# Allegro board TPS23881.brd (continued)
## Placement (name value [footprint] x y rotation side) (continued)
CB142  0.1U/6.3V/X5R-C1  [SM0201_C]  126.11 34.16 90 bottom
CB143  0.1U/6.3V/X5R-C1  [SM0201_C]  107.82 33.78 90 bottom
CB144  0.1U/6.3V/X5R-C1  [SM0201_C]  89.53 33.78 90 bottom
CB145  0.1U/6.3V/X5R-C1  [SM0201_C]  71.25 33.78 90 bottom
CB146  0.1U/6.3V/X5R-C1  [SM0201_C]  52.96 33.78 90 bottom
CB147  0.1U/6.3V/X5R-C1  [SM0201_C]  34.67 33.78 90 bottom
CB148  0.1U/6.3V/X5R-C1  [SM0201_C]  30.86 32.64 0 bottom
CB149  0.1U/6.3V/X5R-C1  [SM0201_C]  139.06 30.1 0 bottom
CB150  0.1U/6.3V/X5R-C1  [SM0201_C]  120.78 29.72 0 bottom
CB151  0.1U/6.3V/X5R-C1  [SM0201_C]  102.49 29.72 0 bottom
CB152  0.1U/6.3V/X5R-C1  [SM0201_C]  84.2 29.72 0 bottom
CB153  0.1U/6.3V/X5R-C1  [SM0201_C]  65.91 29.72 0 bottom
CB154  0.1U/6.3V/X5R-C1  [SM0201_C]  47.62 29.72 0 bottom
CE1  POS-16TQC100MYF  [SM2917_CD19]  44.45 187.96 90 top
CE2  POS-6TPE221MAP  [SM2917_CD19]  152.02 185.8 270 top
CE3  HEC-100U/80V-FVF  [SMEC103X103_165]  36.45 170.56 0 top
CE4  HEC-100U/80V-FVF  [SMEC103X103_165]  24.89 162.18 180 top
CE5  HEC-100U/80V-FVF  [SMEC103X103_165]  9.65 161.04 0 top
CE6  HEC-100U/80V-FVF  [SMEC103X103_165]  28.06 114.59 0 top
CE7  HEC-100U/80V-FVF  [SMEC103X103_165]  28.04 103.75 0 top
CE8  POS-100U/6.3V-TPE  [SM1512_CB20]  132.87 103 270 top
CE9  POS-100U/6.3V-TPE  [SM1512_CB20]  119.28 93.47 270 top
CE10  POS-6TPE220MAZB  [SM1512_CB20]  126.77 85.85 0 top
CE11  POS-6TPE220MAZB  [SM1512_CB20]  99.01 60.15 270 top
CE12  POS-6TPE220MAZB  [SM1512_CB20]  77.8 55.19 90 top
CE13  POS-6TPE220MAZB  [SM1512_CB20]  64.85 53.7 90 top
CM1  0.22U/16V/X7R-C2  [SM0402_C]  147.41 121.3 270 top
CM2  1U/10V/X5R-C2  [SM0402_C]  61.29 63.83 0 top
CM3  1U/10V/X5R-C2  [SM0402_C]  46.23 67.06 180 top
CM4  1U/10V/X5R-C2  [SM0402_C]  55.37 72.64 90 top
CM5  1U/10V/X5R-C2  [SM0402_C]  61.29 64.85 0 top
CM6  1U/10V/X5R-C2  [SM0402_C]  61.29 61.8 0 top
CM7  1U/10V/X5R-C2  [SM0402_C]  52.96 72.64 90 top
CM8  1U/10V/X5R-C2  [SM0402_C]  61.29 59.64 0 top
CM9  1U/10V/X5R-C2  [SM0402_C]  46.23 63.5 180 top
CM10  1U/10V/X5R-C2  [SM0402_C]  46.23 60.83 180 top
CM11  1U/10V/X5R-C2  [SM0402_C]  51.89 57.73 270 top
CM12  1U/10V/X5R-C2  [SM0402_C]  55.37 57.78 270 top
CM13  1U/10V/X5R-C2  [SM0402_C]  57.78 72.64 90 top
CM14  1U/10V/X5R-C2  [SM0402_C]  51.94 72.64 90 top
CM15  1U/10V/X5R-C2  [SM0402_C]  57.78 57.78 270 top
CM16  1U/10V/X5R-C2  [SM0402_C]  52.96 57.78 270 top
CM17  1U/10V/X5R-C2  [SM0402_C]  46.23 62.23 180 top
CM18  1U/10V/X5R-C2  [SM0402_C]  61.29 60.66 0 top
CM19  1U/10V/X5R-C2  [SM0402_C]  54.15 72.64 90 top
CM20  1U/10V/X5R-C2  [SM0402_C]  61.29 62.81 0 top
CM21  1U/10V/X5R-C2  [SM0402_C]  56.57 57.78 270 top
CM22  1U/10V/X5R-C2  [SM0402_C]  56.57 72.64 90 top
CM23  1U/10V/X5R-C2  [SM0402_C]  54.1 57.78 270 top
CM24  1U/10V/X5R-C2  [SM0402_C]  46.81 71.96 180 top
CM25  0.22U/16V/X7R-C2  [SM0402_C]  137.92 121.28 270 top
CM26  0.22U/16V/X7R-C2  [SM0402_C]  139.06 121.28 270 top
CM27  0.22U/16V/X7R-C2  [SM0402_C]  142.11 121.28 270 top
CM28  0.22U/16V/X7R-C2  [SM0402_C]  143.26 121.28 270 top
CM29  0.22U/16V/X7R-C2  [SM0402_C]  146.3 121.28 270 top
CM30  0.22U/16V/X7R-C2  [SM0402_C]  150.5 121.28 270 top
CM31  0.22U/16V/X7R-C2  [SM0402_C]  151.64 121.28 270 top
CM32  -  [SM0402_C]  53.85 112.48 90 top
CM33  -  [SM0402_C]  54.86 112.48 90 top
CM34  -  [SM0402_C]  56.32 112.48 90 top
CM35  -  [SM0402_C]  57.34 112.48 90 top
CM36  -  [SM0402_C]  58.74 112.48 90 top
CM37  -  [SM0402_C]  59.75 112.48 90 top
CM38  -  [SM0402_C]  61.21 112.48 90 top
CM39  -  [SM0402_C]  62.23 112.48 90 top
CM40  -  [SM0402_C]  55.12 109.05 90 top
CM41  -  [SM0402_C]  56.13 109.05 90 top
CM42  -  [SM0402_C]  59.94 108.93 90 top
CM43  -  [SM0402_C]  60.96 108.93 90 top
CM44  0.22U/16V/X7R-C2  [SM0402_C]  91.34 99.16 180 top
CM45  0.22U/16V/X7R-C2  [SM0402_C]  96.84 95 180 top
CM46  -  [SM0402_C]  66.29 84.58 270 top
CM47  -  [SM0402_C]  67.31 84.58 270 top
CM48  -  [SM0402_C]  55.68 83.44 270 top
CM49  -  [SM0402_C]  56.69 83.44 270 top
CM50  -  [SM0402_C]  53.04 77.34 90 top
CM51  -  [SM0402_C]  54.05 77.34 90 top
CM52  -  [SM0402_C]  55.45 77.34 90 top
CM53  -  [SM0402_C]  56.46 77.34 90 top
CM54  -  [SM0402_C]  54.23 75.18 90 top
CM55  -  [SM0402_C]  55.24 75.18 90 top
CM56  -  [SM0402_C]  56.64 75.18 90 top
CM57  -  [SM0402_C]  57.66 75.18 90 top
CM58  -  [SM0402_C]  43.94 63.37 180 top
CM59  -  [SM0402_C]  43.94 62.36 180 top
CM60  -  [SM0402_C]  55.5 55.37 270 top
CM61  -  [SM0402_C]  56.52 55.37 270 top
CM62  -  [SM0402_C]  54.23 52.32 270 top
CM63  -  [SM0402_C]  55.24 52.32 270 top
CM64  0.22U/16V/X7R-C2  [SM0402_C]  140.08 179.07 0 bottom
CM65  0.22U/16V/X7R-C2  [SM0402_C]  130.94 141.48 270 bottom
CM66  0.22U/16V/X7R-C2  [SM0402_C]  138.94 121.03 90 bottom
CM67  0.22U/16V/X7R-C2  [SM0402_C]  137.92 121.03 90 bottom
CM68  -  [SM0402_C]  58.55 108.97 90 bottom
CM69  -  [SM0402_C]  57.53 108.97 90 bottom
CM70  -  [SM0402_C]  63.37 108.93 90 bottom
CM71  -  [SM0402_C]  62.36 108.93 90 bottom
CM72  0.22U/16V/X7R-C2  [SM0402_C]  140.74 100.08 180 bottom
CM73  -  [SM0402_C]  62.1 83.44 270 bottom
CM74  -  [SM0402_C]  61.09 83.44 270 bottom
CM75  -  [SM0402_C]  58.88 83.44 270 bottom
CM76  -  [SM0402_C]  57.86 83.44 270 bottom
CM77  -  [SM0402_C]  68.45 83.31 270 bottom
CM78  -  [SM0402_C]  67.44 83.31 270 bottom
CM79  -  [SM0402_C]  124.59 47.19 180 bottom
CM80  -  [SM0402_C]  124.59 46.18 180 bottom
CM81  -  [SM0402_C]  23.06 39.37 90 bottom
CM82  -  [SM0402_C]  22.05 39.37 90 bottom
CM83  -  [SM0402_C]  131.27 37.08 90 bottom
CM84  -  [SM0402_C]  130.25 37.08 90 bottom
CM85  -  [SM0402_C]  112.98 36.7 90 bottom
CM86  -  [SM0402_C]  111.96 36.7 90 bottom
CM87  -  [SM0402_C]  94.69 36.7 90 bottom
CM88  -  [SM0402_C]  93.68 36.7 90 bottom
CM89  -  [SM0402_C]  76.4 36.7 90 bottom
CM90  -  [SM0402_C]  75.39 36.7 90 bottom
CM91  -  [SM0402_C]  58.12 36.7 90 bottom
CM92  -  [SM0402_C]  57.1 36.7 90 bottom
CM93  -  [SM0402_C]  39.83 36.7 90 bottom
CM94  -  [SM0402_C]  38.81 36.7 90 bottom
CN1  USB3.2-9F-A-RA  [USB3A_WU3R-09]  108.03 66.61 90 bottom
CN2  USB3.1-GEN2-A  [USB31AV_UAA131C-40021]  82.35 45.68 0 bottom
CV1  1000P/2KV-C6  [SM1206_C]  26.37 13.67 270 top
CV8  1000P/2KV-C6  [SM1206_C]  151.76 42.29 90 top
D1  BAT54C  [SOT23-AAC]  74.57 142.88 90 bottom
D2  BAT54H  [SOD323]  87.53 106.05 90 top
D5  YEU25CA0505AC  [DFN10_2D5X1P05H06]  112.22 53.75 270 top
D7  YEU25CA0505AC  [DFN10_2D5X1P05H06]  105.23 66.55 270 top
D8  YEU25CA0505AC  [DFN10_2D5X1P05H06]  82.25 51.89 0 top
D9  YEU25CA0505AC  [DFN10_2D5X1P05H06]  90.17 191.64 0 top
D10  YEU25CA0505AC  [DFN10_2D5X1P05H06]  90.17 191.64 180 bottom
D11  YEU25CA0505AC  [DFN10_2D5X1P05H06]  63.07 49.86 180 bottom
D12  PDWL5R0R35-DFN1006  [DFN1006-2L]  23.62 193.29 90 top
D13  PDWL5R0R35-DFN1006  [DFN1006-2L]  23.62 194.69 90 top
D14  SMB30J58CA  [SMB_TVS]  4.83 12.19 0 top
D15  SMB30J58CA  [SMB_TVS]  4.83 12.19 0 bottom
D16  YEU25CA0505AC  [DFN10_2D5X1P05H06]  23.88 25.78 0 bottom
D17  SMB30J58CA  [SMB_TVS]  4.83 7.75 0 top
D18  SMB30J58CA  [SMB_TVS]  4.83 7.75 0 bottom
D19  YEU25CA0505AC  [DFN10_2D5X1P05H06]  27.25 25.73 0 bottom
D20  SMB30J58CA  [SMB_TVS]  29.84 9.73 90 top
D21  YEU25CA0505AC  [DFN10_2D5X1P05H06]  41.15 22.86 0 bottom
D22  SMB30J58CA  [SMB_TVS]  29.84 9.73 90 bottom
D23  YEU25CA0505AC  [DFN10_2D5X1P05H06]  44.45 22.86 0 bottom
D24  YEU25CA0505AC  [DFN10_2D5X1P05H06]  59.44 22.86 0 bottom
D25  SMB30J58CA  [SMB_TVS]  50.04 9.73 90 top
D26  SMB30J58CA  [SMB_TVS]  50.04 9.73 90 bottom
D27  YEU25CA0505AC  [DFN10_2D5X1P05H06]  62.74 22.86 0 bottom
D28  SMB30J58CA  [SMB_TVS]  70.23 9.73 90 top
D29  YEU25CA0505AC  [DFN10_2D5X1P05H06]  77.72 22.86 0 bottom
D30  SMB30J58CA  [SMB_TVS]  70.23 9.73 90 bottom
D31  YEU25CA0505AC  [DFN10_2D5X1P05H06]  81.03 22.86 0 bottom
D32  YEU25CA0505AC  [DFN10_2D5X1P05H06]  96.01 22.86 0 bottom
D33  SMB30J58CA  [SMB_TVS]  90.42 9.73 90 top
D34  SMB30J58CA  [SMB_TVS]  90.42 9.73 90 bottom
D35  YEU25CA0505AC  [DFN10_2D5X1P05H06]  99.31 22.86 0 bottom
D36  SMB30J58CA  [SMB_TVS]  110.62 9.73 90 top
D37  YEU25CA0505AC  [DFN10_2D5X1P05H06]  114.3 22.86 0 bottom
D38  SMB30J58CA  [SMB_TVS]  110.62 9.73 90 bottom
D39  YEU25CA0505AC  [DFN10_2D5X1P05H06]  117.6 22.86 0 bottom
D40  SMB30J58CA  [SMB_TVS]  130.81 9.73 90 top
D41  SMB30J58CA  [SMB_TVS]  130.81 9.73 90 bottom
D42  YEU25CA0505AC  [DFN10_2D5X1P05H06]  132.59 23.24 0 bottom
D43  YEU25CA0505AC  [DFN10_2D5X1P05H06]  135.89 23.24 0 bottom
D44  YEU25CA0505AC  [DFN10_2D5X1P05H06]  138.07 48.64 90 bottom
D45  YEU25CA0505AC  [DFN10_2D5X1P05H06]  137.97 51.94 90 bottom
D46  S100  [SMA]  4.7 52.96 0 bottom
D47  S100  [SMA]  12.19 52.96 0 bottom
D48  S100  [SMA]  4.7 64.26 0 bottom
D49  S100  [SMA]  12.19 64.26 0 bottom
D50  S100  [SMA]  19.68 52.96 0 bottom
D51  S100  [SMA]  19.68 64.26 0 bottom
D52  S100  [SMA]  27.18 52.96 0 bottom
D53  S100  [SMA]  27.18 64.26 0 bottom
D54  S7239-300Y  [SOD323]  109.3 50.88 180 top
D55  YEU25CA0505AC  [DFN10_2D5X1P05H06]  99.19 49.78 0 bottom
D56  YEU25CA0505AC  [DFN10_2D5X1P05H06]  102.62 49.78 0 bottom
D57  YEU25CA0505AC  [DFN10_2D5X1P05H06]  105.92 49.78 180 bottom
D58  1N4148WS  [SOD323]  2.16 176.02 270 bottom
D59  SMBJ58A  [SMB]  3.17 182.63 270 bottom
D60  SMBJ58A  [SMB]  24.59 166.57 0 bottom
D61  SMBJ58A  [SMB]  20.7 183.26 270 top
D62  SMBJ26A  [SMB]  20.7 183.39 270 bottom
D63  SMBJ58A  [SMB]  10.24 156.29 180 bottom
D64  CZRQC52C3V9A-HF  [SM0402_D]  147.09 99.82 90 bottom
D65  BAT54H  [SOD323]  87.53 110.24 90 top
D66  YEU25CA0505AC  [DFN10_2D5X1P05H06]  66.62 49.86 0 bottom
DB1  PH127-5X2-S  [CONHS5X2P127_WP]  118.11 63.25 270 bottom
DC_IN1  ATX-6P-P4.2  [ATX6P-WP]  11.89 173.2 0 bottom
F1  1206SMD200  [SM1206_F]  4.52 54.94 180 top
F2  1206SMD200  [SM1206_F]  12.01 54.94 180 top
F3  1206SMD200  [SM1206_F]  4.52 66.24 180 top
F4  1206SMD200  [SM1206_F]  12.01 66.24 180 top
F5  1206SMD200  [SM1206_F]  19.51 54.94 180 top
F6  1206SMD200  [SM1206_F]  19.51 66.24 180 top
F7  1206SMD200  [SM1206_F]  27 54.94 180 top
F8  1206SMD200  [SM1206_F]  27 66.24 180 top
F9  0805SMD100  [SM0805_F]  104.47 50.24 270 top
FB1  30/3A-L3  [SM0603_B]  145.06 79.25 180 bottom
FB2  60/3A-L3  [SM0603_B]  141.73 78.74 270 top
FB3  60/3A-L3  [SM0603_B]  81.23 81.99 0 top
FB5  120-L2  [SM0402_B]  136.14 134.11 270 top
FB7  @30/3A-L3  [SM0603_B]  139.95 177.93 0 top
FB8  600/2A-L5  [SM0805_B]  11.38 13.41 90 top
FB9  600/2A-L5  [SM0805_B]  14.05 13.41 90 top
FB10  600/2A-L5  [SM0805_B]  19 13.41 90 top
FB11  600/2A-L5  [SM0805_B]  23.19 13.41 90 top
FB12  600/2A-L5  [SM0805_B]  33.53 13.46 90 top
FB13  600/2A-L5  [SM0805_B]  37.72 13.46 90 top
FB16  600/2A-L5  [SM0805_B]  53.72 13.46 90 top
FB17  600/2A-L5  [SM0805_B]  57.91 13.46 90 top
FB18  600/2A-L5  [SM0805_B]  73.91 13.46 90 top
FB19  600/2A-L5  [SM0805_B]  78.11 13.46 90 top
FB20  600/2A-L5  [SM0805_B]  94.11 13.46 90 top
FB21  600/2A-L5  [SM0805_B]  98.3 13.46 90 top
FB22  600/2A-L5  [SM0805_B]  114.3 13.46 90 top
FB23  600/2A-L5  [SM0805_B]  118.49 13.46 90 top
FB26  600/2A-L5  [SM0805_B]  134.49 13.46 90 top
FB27  600/2A-L5  [SM0805_B]  138.68 13.46 90 top
FB28  PBY160808T-331Y-N  [SM0603_B]  101.75 92.33 0 top
FB29  PBY160808T-331Y-N  [SM0603_B]  101.75 90.42 0 bottom
FB30  PBY160808T-331Y-N  [SM0603_B]  98.83 80.9 270 bottom
FB31  PBY160808T-331Y-N  [SM0603_B]  104.17 83.57 90 top
FB32  PBY160808T-331Y-N  [SM0603_B]  102.11 89.79 0 top
FB33  PBY160808T-331Y-N  [SM0603_B]  95.53 80.14 0 bottom
FB34  PBY160808T-331Y-N  [SM0603_B]  101.75 88.77 0 bottom
FB35  30/3A-L3  [SM0603_B]  45.67 98.88 0 top
FB36  30/3A-L3  [SM0603_B]  44.65 59.51 180 top
FB37  30/3A-L3  [SM0603_B]  45.67 89.23 0 top
FB38  30/3A-L3  [SM0603_B]  10.67 180.85 180 top
FB39  120-L2  [SM0402_B]  151.5 98.9 270 top
FB40  120-L3  [SM0603_B]  150.11 153.42 180 bottom
FB41  120-L3  [SM0603_B]  150.11 155.32 0 bottom
FB46  30/3A-L3  [SM0603_B]  75.64 149.56 180 top
FB47  @600/2A-L5  [SM0805_B]  2.59 16.38 270 top
FB48  @600/2A-L5  [SM0805_B]  2.59 16.38 270 bottom
FB49  @600/2A-L5  [SM0805_B]  148.74 62.23 270 bottom
FB50  @600/2A-L5  [SM0805_B]  148.74 62.23 270 top
FL1  @GCMF1210PA-900T1  [CM-CHOKE-1210-4P]  157.48 177.42 180 bottom
FL2  ACT45B/51UH  [CM-CHOKE-ACT45B-4P]  33.91 191.9 0 bottom
H1  @HOLE  [HOLETB354C158D158N-V8_OSP]  11.25 188 0 top
H2  @HOLE  [HOLETB354C158D158N-V8_OSP]  148.75 165.1 0 top
H3  @HOLE  [HOLETB354C158D158N-V8_OSP]  11.25 28.1 0 top
H4  @HOLE  [HOLETB354C158D158N-V8_OSP]  148.75 28.1 0 top
HDMI1  HDMI-19P-A-VERTICAL-S  [HDMI-S19PV_CHD-8X0A-190]  102.36 44.45 0 bottom
J1  203456-0003  [BTBS-BGA699-MIRMEZ-203456003]  80 125.56 0 top
J4  @PH127-5X2-S  [CONHS5X2P127_WP]  121.92 123.95 270 bottom
J7  @PH254-3X1  [CONHD3X1]  34.04 70.87 180 bottom
J11  PH254-4X1  [CONHD4X1]  33.91 78.74 180 bottom
J13  PH254-4X1  [CONHD4X1]  33.91 74.8 180 bottom
J14  BTB050-60X2-H3.25-S  [BTBS-60X2P05-QSH-01]  106.25 168.26 0 top
JPPCIE1  PH254-2X1  [CONHD2X1]  33.78 82.68 180 bottom
JPSON1  PH254-2X1  [CONHD2X1]  157.61 36.83 270 bottom
JSIM1  SIM-6-S  [SIM_N0601B010]  122.56 183.46 0 bottom
JSIM2  SIM-6-S  [SIM_N0601B010]  137.1 183.46 0 bottom
L1  GTHW2012PC-900T1  [CM-CHOKE-2012-4P]  109.3 52.86 0 top
L2  GTHW2012PC-900T1  [CM-CHOKE-2012-4P]  109.3 54.66 0 top
L3  GCMF2012PA-900T  [CM-CHOKE-2012-4P]  81.03 54.81 270 top
L4  GCMF2012PA-900T  [CM-CHOKE-2012-4P]  102.18 67.69 0 top
L5  GCMF2012PA-900T  [CM-CHOKE-2012-4P]  83.31 54.81 270 top
L6  GCMF2012PA-900T  [CM-CHOKE-2012-4P]  102.18 65.41 0 top
L7  GTHW2012PC-900T1  [CM-CHOKE-2012-4P]  64.01 52.45 270 bottom
L8  GCMF2012PA-900T  [CM-CHOKE-2012-4P]  97.92 52.7 270 bottom
L9  GCMF2012PA-900T  [CM-CHOKE-2012-4P]  99.95 52.7 270 bottom
L10  GCMF2012PA-900T  [CM-CHOKE-2012-4P]  101.85 52.7 270 bottom
L11  GCMF2012PA-900T  [CM-CHOKE-2012-4P]  103.76 52.7 270 bottom
L12  SIC2717/10UH  [SER2918H_LS-178]  20.84 145.2 0 top
LANACT1  LED0603-G  [SM0603_LED]  27.76 41.22 180 bottom
LANACT2  LED0603-G  [SM0603_LED]  44.58 38.35 0 bottom
LANACT3  LED0603-G  [SM0603_LED]  62.87 38.35 0 bottom
LANACT4  LED0603-G  [SM0603_LED]  81.15 38.35 0 bottom
LANACT5  LED0603-G  [SM0603_LED]  99.44 38.35 0 bottom
LANACT6  LED0603-G  [SM0603_LED]  117.73 38.35 0 bottom
LANACT7  LED0603-G  [SM0603_LED]  136.02 38.73 0 bottom
LANACT8  LED0603-G  [SM0603_LED]  125.48 58.93 90 bottom
LANLINK1  LED0805-G+Y  [SM0805_LED-4]  31.75 39.62 180 bottom
LANLINK2  LED0805-G+Y  [SM0805_LED-4]  47.62 37.47 270 bottom
LANLINK3  LED0805-G+Y  [SM0805_LED-4]  65.91 37.47 270 bottom
LANLINK4  LED0805-G+Y  [SM0805_LED-4]  84.2 37.47 270 bottom
LANLINK5  LED0805-G+Y  [SM0805_LED-4]  102.87 37.21 270 bottom
LANLINK6  LED0805-G+Y  [SM0805_LED-4]  120.78 37.47 270 bottom
LANLINK7  LED0805-G+Y  [SM0805_LED-4]  139.06 37.85 270 bottom
LANLINK8  LED0805-G+Y  [SM0805_LED-4]  127.76 59.05 270 bottom
LED1  LED0603-G  [SM0603_LED]  128.27 129.92 180 bottom
LED2  LED0603-G  [SM0603_LED]  128.27 131.83 180 bottom
MCUCON1  PH254-3X1  [CONHD3X1]  157.61 165.23 270 bottom
MHB1  STANDOFF-M3X1.5-T1.4  [HOLEC256D177-PT]  100.89 184.91 180 bottom
MHB2  STANDOFF-M3X1.5-T1.4  [HOLEC256D177-PT]  110.82 184.91 180 bottom
MHE1  STANDOFF-M3X2.45  [HOLEC256D166-PT]  141.49 156.9 180 bottom
MHM1  STANDOFF-M3X6.6  [HOLEC256D166-PT]  146.81 36.05 0 top
NCSI1  WF100-10/BM10B-SRSS-TB  [WF100S-10P-BM10B-SRSS]  154.8 76.7 270 bottom
NGFF1  NGFF-75P,H8.5-B  [M2-67H85-B-3052]  150.42 184.92 90 bottom
NMEA0183  WF200-8/B08B-PASK(LF)(SN)  [WF200D-8P-PASK]  54.55 197.56 180 bottom
NMEA2000  WF200-8/B08B-PASK(LF)(SN)  [WF200D-8P-PASK]  29.55 197.56 180 bottom
NOREF  -  []  67.94 89.56 90 top
NOREF#2  -  []  8.87 0.16 0 top
NOREF#3  -  []  53.26 58.6 270 top
NOREF#4  -  []  139.34 175.26 0 top
NOREF#5  -  []  144.83 173.69 0 top
NOREF#6  -  []  134.4 146.05 0 top
NOREF#7  -  []  45.42 62.53 270 top
NOREF#8  -  []  106.93 139.97 270 top
NOREF#9  -  []  27.55 194.36 90 top
NOREF#10  -  []  124.64 38.96 0 top
NOREF#11  -  []  28.63 27.46 90 top
NOREF#12  -  []  7.44 158.19 0 top
NOREF#13  -  []  57.86 83.91 270 top
NOREF#14  -  []  89.61 28.69 0 top
NOREF#15  -  []  62.89 67.31 0 top
NOREF#16  -  []  77.42 18.72 0 top
NOREF#17  -  []  97.92 17.44 90 top
NOREF#18  -  []  76.58 18.41 90 top
NOREF#19  -  []  146.14 109.21 270 top
NOREF#20  -  []  95.61 57.61 0 top
NOREF#21  -  []  62.94 189.03 270 top
NOREF#22  -  []  61.8 174.55 0 top
NOREF#23  -  []  130.1 136.22 90 top
NOREF#24  -  []  38.11 36.27 90 top
NOREF#25  -  []  138.69 121.53 90 top
NOREF#26  -  []  134.06 144.6 90 top
NOREF#27  -  []  79.73 108.03 0 top
NOREF#28  -  []  114.38 133.68 0 top
NOREF#29  -  []  64.57 67.77 90 top
NOREF#30  -  []  128.52 174.5 0 top
NOREF#31  -  []  119.08 181.03 0 top
NOREF#32  -  []  66.88 95.07 0 top
NOREF#33  -  []  141.34 177.92 270 top
NOREF#34  -  []  119.94 134.92 270 top
NOREF#35  -  []  134.48 34.85 0 top
NOREF#36  -  []  140.59 47.75 0 top
NOREF#37  -  []  138.71 35.05 0 top
NOREF#38  -  []  144.65 17.4 90 top
NOREF#39  -  []  133.38 133.6 0 top
NOREF#40  -  []  69.88 79.53 90 top
NOREF#41  -  []  13.84 117.12 90 top
NOREF#42  -  []  129.07 129.52 90 top
NOREF#43  -  []  71.86 82.5 0 top
NOREF#44  -  []  54.31 77.85 270 top
NOREF#45  -  []  14.81 109.19 90 top
NOREF#46  -  []  74.69 36.88 270 top
NOREF#47  -  []  67.56 84.07 90 top
NOREF#48  -  []  68.28 181.94 0 top
NOREF#49  -  []  54.56 40.94 0 top
NOREF#50  -  []  35.23 41.45 270 top
NOREF#51  -  []  17.98 34.4 90 top
NOREF#52  -  []  33.54 33.48 90 top
NOREF#53  -  []  125.86 36.97 270 top
NOREF#54  -  []  110.36 23.76 270 top
NOREF#55  -  []  42.44 108.23 90 top
NOREF#56  -  []  148.01 131.11 270 top
NOREF#57  -  []  30.51 37.59 0 top
NOREF#58  -  []  143.28 105.66 0 top
NOREF#59  -  []  126.19 30.09 0 top
NOREF#60  -  []  68.15 84.12 270 top
NOREF#61  -  []  37.07 25.22 90 top
NOREF#62  -  []  126.44 99.14 0 top
NOREF#63  -  []  126.57 52.46 0 top
NOREF#64  -  []  129.95 37.9 0 top
NOREF#65  -  []  53.31 47.6 0 top
NOREF#66  -  []  98.18 34.47 270 top
NOREF#67  -  []  120.42 34.67 0 top
NOREF#68  -  []  132.36 73.37 270 top
NOREF#69  -  []  20.38 26.54 0 top
NOREF#70  -  []  157.66 184.65 90 top
NOREF#71  -  []  92.2 36.31 90 top
NOREF#72  -  []  52.2 72.14 90 top
NOREF#73  -  []  134.06 146.89 90 top
NOREF#74  -  []  92.93 100.68 0 top
NOREF#75  -  []  110.86 23.8 270 top
NOREF#76  -  []  84.51 32.65 270 top
NOREF#77  -  []  60.81 67.01 0 top
NOREF#78  -  []  128.51 25.6 0 top
NOREF#79  -  []  37 177.8 0 top
NOREF#80  -  []  67.36 157.94 90 top
NOREF#81  -  []  60.01 112.99 270 top
NOREF#82  -  []  40.64 17.4 90 top
NOREF#83  -  []  99.55 51.83 90 top
NOREF#84  -  []  83.11 58.42 270 top
NOREF#85  -  []  55.68 83.91 270 top
NOREF#86  -  []  131.5 88.39 0 top
NOREF#87  -  []  164.64 76.33 0 top
NOREF#88  -  []  34.75 29.71 0 top
NOREF#89  -  []  40.96 25.58 0 top
NOREF#90  -  []  19.01 70.12 90 top
NOREF#91  -  []  128.22 174.55 270 top
NOREF#92  -  []  17.65 35.06 90 top
NOREF#93  -  []  66.85 176.61 90 top
NOREF#94  -  []  54.31 148.03 0 top
NOREF#95  -  []  43.68 18.41 90 top
NOREF#96  -  []  130.25 173.81 90 top
NOREF#97  -  []  61.8 84.25 270 top
NOREF#98  -  []  139.34 174.12 0 top
NOREF#99  -  []  43.05 36.59 270 top
NOREF#100  -  []  164.19 76.76 0 top
NOREF#101  -  []  134.4 150.11 0 top
NOREF#102  -  []  61.33 34.47 0 top
NOREF#103  -  []  87.66 93.5 90 top
NOREF#104  -  []  42.91 36.63 0 top
NOREF#105  -  []  157.42 111 0 top
NOREF#106  -  []  76.89 105.46 270 top
NOREF#107  -  []  101.35 52.51 90 top
NOREF#108  -  []  101.73 139.42 270 top
NOREF#109  -  []  150.57 176.35 0 top
NOREF#110  -  []  84.51 28.97 270 top
NOREF#111  -  []  134.51 44.63 270 top
NOREF#112  -  []  151.22 102.19 270 top
NOREF#113  -  []  31.63 190.65 0 top
NOREF#114  -  []  145.16 92.48 90 top
NOREF#115  -  []  45.76 67.06 0 top
NOREF#116  -  []  34.06 190.91 90 top
NOREF#117  -  []  61.79 60.41 90 top
NOREF#118  -  []  131.56 44.63 0 top
NOREF#119  -  []  102.79 28.69 90 top
NOREF#120  -  []  120.47 31.93 0 top
NOREF#121  -  []  20.29 115.75 0 top
NOREF#122  -  []  143.18 70.92 270 top
NOREF#123  -  []  88.76 34.09 0 top
NOREF#124  -  []  30.05 38.02 270 top
NOREF#125  -  []  67.86 26.04 0 top
NOREF#126  -  []  64.97 176.61 0 top
NOREF#127  -  []  130.42 24.18 270 top
NOREF#128  -  []  68.28 181.94 90 top
NOREF#129  -  []  124.92 54.43 0 top
NOREF#130  -  []  62.94 177.34 0 top
NOREF#131  -  []  92.74 109.05 270 top
NOREF#132  -  []  10.41 65.44 0 top
NOREF#133  -  []  79.9 33.86 90 top
NOREF#134  -  []  126.06 54.43 90 top
NOREF#135  -  []  149.17 72.09 270 top
NOREF#136  -  []  55.93 82.93 90 top
NOREF#137  -  []  92.49 109.09 90 top
NOREF#138  -  []  148.26 99.44 0 top
NOREF#139  -  []  121.41 18.41 90 top
NOREF#140  -  []  31.83 30.34 90 top
NOREF#141  -  []  82.6 27.75 270 top
NOREF#142  -  []  102.16 139.88 270 top
NOREF#143  -  []  74.5 18.72 0 top
NOREF#144  -  []  41.1 25.62 90 top
NOREF#145  -  []  40.44 96.44 270 top
NOREF#146  -  []  117.81 154.38 270 top
NOREF#147  -  []  139.9 89.46 270 top
NOREF#148  -  []  56.82 57.28 90 top
NOREF#149  -  []  126.25 33.86 90 top
NOREF#150  -  []  121.08 28.69 90 top
NOREF#151  -  []  62.66 109.74 270 top
NOREF#152  -  []  62.18 51.38 90 top
NOREF#153  -  []  71.32 31.48 0 top
NOREF#154  -  []  137.27 44.7 0 top
NOREF#155  -  []  129.24 163.5 0 top
NOREF#156  -  []  24.17 28.5 0 top
NOREF#157  -  []  76.14 197.59 0 top
NOREF#158  -  []  146.25 129.49 0 top
NOREF#159  -  []  104.87 2.26 90 top
NOREF#160  -  []  116.18 42.85 0 top
NOREF#161  -  []  102.22 29.72 0 top
NOREF#162  -  []  70.85 36.63 0 top
NOREF#163  -  []  100.15 138 0 top
NOREF#164  -  []  70.79 141.86 0 top
NOREF#165  -  []  98.5 66.22 0 top
NOREF#166  -  []  31.17 35.29 90 top
NOREF#167  -  []  105.71 26.34 270 top
NOREF#168  -  []  47.96 140 0 top
NOREF#169  -  []  110.99 36.27 0 top
NOREF#170  -  []  144.86 177.09 0 top
NOREF#171  -  []  45.82 24.99 90 top
NOREF#172  -  []  83.93 33.78 0 top
NOREF#173  -  []  128.19 35.89 90 top
NOREF#174  -  []  96.77 18.41 90 top
NOREF#175  -  []  132.4 25.96 0 top
NOREF#176  -  []  136.88 89.97 270 top
NOREF#177  -  []  40.44 104.22 90 top
NOREF#178  -  []  55.36 25.22 90 top
NOREF#179  -  []  122.1 154.76 0 top
NOREF#180  -  []  88.4 33.48 90 top
NOREF#181  -  []  63.68 24.54 90 top
NOREF#182  -  []  37.34 17.44 90 top
NOREF#183  -  []  110.11 139.67 270 top
NOREF#184  -  []  149.2 75.87 0 top
NOREF#185  -  []  103.3 139.88 270 top
NOREF#186  -  []  78.44 26.15 270 top
NOREF#187  -  []  22.38 22.1 0 top
NOREF#188  -  []  125.43 182.04 0 top
NOREF#189  -  []  119.38 181.99 0 top
NOREF#190  -  []  57.96 98.88 0 top
NOREF#191  -  []  33.26 33.48 0 top
NOREF#192  -  []  84.07 18.41 90 top
NOREF#193  -  []  54.31 168.35 0 top
NOREF#194  -  []  71.02 26.12 270 top
NOREF#195  -  []  144.86 175.08 90 top
NOREF#196  -  []  134.82 174.57 90 top
NOREF#197  -  []  50.9 52.27 0 top
NOREF#198  -  []  62.09 34.47 0 top
NOREF#199  -  []  23.28 28.49 0 top
NOREF#200  -  []  65.1 66.62 0 top
NOREF#201  -  []  11.2 126.39 90 top
NOREF#202  -  []  115.77 73.58 0 top
NOREF#203  -  []  15.06 20.82 90 top
NOREF#204  -  []  124.46 18.41 90 top
NOREF#205  -  []  68.35 152.02 0 top
NOREF#206  -  []  136.56 64.77 0 top
NOREF#207  -  []  52.55 103.53 0 top
NOREF#208  -  []  65.61 33.92 0 top
NOREF#209  -  []  128 31.75 0 top
NOREF#210  -  []  6.79 161.35 90 top
NOREF#211  -  []  6.87 155.1 0 top
NOREF#212  -  []  19.75 25.93 90 top
NOREF#213  -  []  141.6 18.41 90 top
NOREF#214  -  []  136.22 79.55 0 top
NOREF#215  -  []  53.84 147.19 90 top
NOREF#216  -  []  115.52 120.57 0 top
NOREF#217  -  []  56.38 109.56 90 top
NOREF#218  -  []  123.52 78.28 0 top
NOREF#219  -  []  140.26 128.07 270 top
NOREF#220  -  []  134.37 149.35 0 top
NOREF#221  -  []  34.67 18.41 90 top
NOREF#222  -  []  36.53 31.23 90 top
NOREF#223  -  []  58.12 37.17 270 top
NOREF#224  -  []  135.69 90.81 0 top
NOREF#225  -  []  52.15 37.86 0 top
NOREF#226  -  []  151.41 15.57 0 top
NOREF#227  -  []  138.42 176.56 0 top
NOREF#228  -  []  62.42 101.51 90 top
NOREF#229  -  []  30.59 36.7 0 top
NOREF#230  -  []  126.57 51.3 90 top
NOREF#231  -  []  131.78 66.3 0 top
NOREF#232  -  []  36.27 39.07 90 top
NOREF#233  -  []  123.39 154.61 270 top
NOREF#234  -  []  134.44 159.05 0 top
NOREF#235  -  []  57.04 113.3 270 top
NOREF#236  -  []  141.25 62.1 0 top
NOREF#237  -  []  19.76 29.32 0 top
NOREF#238  -  []  108.51 27.42 90 top
NOREF#239  -  []  137.77 42.09 0 top
NOREF#240  -  []  39.45 110.16 0 top
NOREF#241  -  []  79.73 109.3 90 top
NOREF#242  -  []  30.65 28.96 0 top
NOREF#243  -  []  74.14 199.69 0 top
NOREF#244  -  []  128.87 0.16 0 top
NOREF#245  -  []  28.96 38.89 90 top
NOREF#246  -  []  13.72 80.04 90 top
NOREF#247  -  []  109.68 26.4 0 top
NOREF#248  -  []  136.81 113.65 90 top
NOREF#249  -  []  42.88 112.06 270 top
NOREF#250  -  []  34.75 26.43 270 top
NOREF#251  -  []  119.18 27.75 270 top
NOREF#252  -  []  124.45 45.34 0 top
NOREF#253  -  []  91.03 100.95 0 top
NOREF#254  -  []  151.08 72.34 90 top
NOREF#255  -  []  91.94 23.8 0 top
NOREF#256  -  []  126.19 26.81 270 top
NOREF#257  -  []  121.78 27.56 0 top
NOREF#258  -  []  98.76 110.79 0 top
NOREF#259  -  []  88.76 37.72 0 top
NOREF#260  -  []  136.78 183.13 90 top
NOREF#261  -  []  71.49 36.63 0 top
NOREF#262  -  []  142.29 26.72 270 top
NOREF#263  -  []  124.79 137.97 0 top
NOREF#264  -  []  137.46 28.13 270 top
NOREF#265  -  []  65.68 188.59 0 top
NOREF#266  -  []  48.13 12.52 270 top
NOREF#267  -  []  124.87 2.26 90 top
NOREF#268  -  []  61.8 181.53 90 top
NOREF#269  -  []  54.55 197.56 90 top
NOREF#270  -  []  25.07 178.56 90 top
NOREF#271  -  []  149.05 151.18 0 top
NOREF#272  -  []  134.23 55.55 0 top
NOREF#273  -  []  102.18 33.29 0 top
NOREF#274  -  []  125.9 32.03 0 top
NOREF#275  -  []  151.82 149.12 90 top
NOREF#276  -  []  108.18 31.79 270 top
NOREF#277  -  []  17.68 81.28 0 top
NOREF#278  -  []  40.17 123.06 0 top
NOREF#279  -  []  82.45 52.7 0 top
NOREF#280  -  []  10.52 74.12 0 top
NOREF#281  -  []  138.25 126.19 0 top
NOREF#282  -  []  40.84 110.69 0 top
NOREF#283  -  []  96.25 59.31 0 top
NOREF#284  -  []  49.78 53.98 270 top
NOREF#285  -  []  143.28 104.52 0 top
NOREF#286  -  []  127.33 74.22 0 top
NOREF#287  -  []  12.22 117.73 0 top
NOREF#288  -  []  67.18 82.8 90 top
NOREF#289  -  []  156.54 178.36 0 top
NOREF#290  -  []  75.46 100.71 0 top
NOREF#291  -  []  72.21 141.43 90 top
NOREF#292  -  []  135.29 136.02 0 top
NOREF#293  -  []  40.39 92.08 270 top
NOREF#294  -  []  131.95 156.97 90 top
NOREF#295  -  []  81.99 26.71 0 top
NOREF#296  -  []  144.86 176.23 90 top
NOREF#297  -  []  89.14 36.63 0 top
NOREF#298  -  []  50.9 53.54 0 top
NOREF#299  -  []  118.19 152.6 0 top
NOREF#300  -  []  20.37 31.99 90 top
NOREF#301  -  []  80.47 18.72 270 top
NOREF#302  -  []  40.01 104.67 90 top
NOREF#303  -  []  115.98 116.71 0 top
NOREF#304  -  []  71.86 84.38 270 top
NOREF#305  -  []  92.7 36.27 0 top
NOREF#306  -  []  139.12 102.67 270 top
NOREF#307  -  []  29.06 27.91 90 top
NOREF#308  -  []  16.97 79.98 90 top
NOREF#309  -  []  127.53 66.57 0 top
NOREF#310  -  []  86.11 26.29 0 top
NOREF#311  -  []  102.23 25.78 0 top
NOREF#312  -  []  81.27 34.52 0 top
NOREF#313  -  []  62.15 69.52 270 top
NOREF#314  -  []  100.15 35.51 0 top
NOREF#315  -  []  46.61 46.51 90 top
NOREF#316  -  []  154.79 12.88 0 top
NOREF#317  -  []  132.21 92.74 90 top
NOREF#318  -  []  119.42 180.72 0 top
NOREF#319  -  []  71.36 32.26 0 top
NOREF#320  -  []  94.86 25.58 90 top
NOREF#321  -  []  70.33 79.96 0 top
NOREF#322  -  []  26.96 41.62 0 top
NOREF#323  -  []  138.56 83.99 90 top
NOREF#324  -  []  18.02 34.54 0 top
NOREF#325  -  []  57.35 76 270 top
NOREF#326  -  []  18.87 80.98 270 top
NOREF#327  -  []  52.15 37.58 90 top
NOREF#328  -  []  120.22 26.34 0 top
NOREF#329  -  []  52.53 145.52 90 top
NOREF#330  -  []  135.97 68.78 90 top
NOREF#331  -  []  48.59 27.7 270 top
NOREF#332  -  []  130.1 133.68 90 top
NOREF#333  -  []  110.03 65.61 90 top
NOREF#334  -  []  117.81 17.09 90 top
NOREF#335  -  []  116.2 73.13 270 top
NOREF#336  -  []  33.86 37.86 270 top
NOREF#337  -  []  157.05 184.29 0 top
NOREF#338  -  []  144.98 188.16 90 top
NOREF#339  -  []  21.02 25.93 90 top
NOREF#340  -  []  9.73 53.8 0 top
NOREF#341  -  []  144.73 92.02 0 top
NOREF#342  -  []  134.11 183.13 90 top
NOREF#343  -  []  106.87 5.46 270 top
NOREF#344  -  []  121.79 136.63 270 top
NOREF#345  -  []  55.12 112.99 270 top
NOREF#346  -  []  133.73 155.55 270 top
NOREF#347  -  []  121.08 30.3 90 top
NOREF#348  -  []  139.47 79.24 90 top
NOREF#349  -  []  53.04 28.69 0 top
NOREF#350  -  []  97.61 17.09 90 top
NOREF#351  -  []  133.86 130.3 90 top
NOREF#352  -  []  129.67 44.06 90 top
NOREF#353  -  []  63.58 35.51 90 top
NOREF#354  -  []  120.47 28.97 0 top
NOREF#355  -  []  93.8 101.65 90 top
NOREF#356  -  []  28.07 36.94 90 top
NOREF#357  -  []  50.06 48.92 0 top
NOREF#358  -  []  145.87 179.25 0 top
NOREF#359  -  []  45.55 177.24 90 top
NOREF#360  -  []  19.56 38.89 90 top
NOREF#361  -  []  52.82 33.48 0 top
NOREF#362  -  []  129.07 131.43 90 top
NOREF#363  -  []  100.66 106.22 270 top
NOREF#364  -  []  58.42 25.62 90 top
NOREF#365  -  []  45.92 146.99 0 top
NOREF#366  -  []  141.3 101.9 270 top
NOREF#367  -  []  43.78 38.75 270 top
NOREF#368  -  []  107.9 30.62 270 top
NOREF#369  -  []  138.89 173.15 270 top
NOREF#370  -  []  135.52 34.85 270 top
NOREF#371  -  []  141.73 102.87 90 top
NOREF#372  -  []  140.16 138.76 90 top
NOREF#373  -  []  121.34 135.18 0 top
NOREF#374  -  []  151.21 135.71 0 top
NOREF#375  -  []  91.39 26.4 0 top
NOREF#376  -  []  131.57 26 90 top
NOREF#377  -  []  146.56 173.2 270 top
NOREF#378  -  []  95.02 106.53 270 top
NOREF#379  -  []  140.03 28.08 270 top
NOREF#380  -  []  83.52 18.72 0 top
NOREF#381  -  []  46.94 33.58 0 top
NOREF#382  -  []  151.76 20.02 90 top
NOREF#383  -  []  127.66 75.06 0 top
NOREF#384  -  []  151.08 75.01 90 top
NOREF#385  -  []  145.59 134.54 270 top
NOREF#386  -  []  151.21 89.61 0 top
NOREF#387  -  []  117.81 18.72 0 top
NOREF#388  -  []  86.16 108.51 270 top
NOREF#389  -  []  55.07 193.42 90 top
NOREF#390  -  []  70.98 27.56 0 top
NOREF#391  -  []  134.06 148.77 0 top
NOREF#392  -  []  139.34 43.97 90 top
NOREF#393  -  []  34.79 28.19 0 top
NOREF#394  -  []  92.87 100.93 0 top
NOREF#395  -  []  47.32 29.58 0 top
NOREF#396  -  []  41 90.27 90 top
NOREF#397  -  []  126.9 160.27 0 top
NOREF#398  -  []  80.38 34.47 0 top
NOREF#399  -  []  36.4 128.32 270 top
NOREF#400  -  []  18.67 179.45 0 top
NOREF#401  -  []  49.21 109.6 0 top
NOREF#402  -  []  18.02 35.18 0 top
NOREF#403  -  []  87.12 25.78 90 top
NOREF#404  -  []  134.82 49.01 0 top
NOREF#405  -  []  127.56 42.3 270 top
NOREF#406  -  []  27.38 38.43 0 top
NOREF#407  -  []  137.67 120.52 90 top
NOREF#408  -  []  139.37 28.44 90 top
NOREF#409  -  []  53.1 33.48 90 top
NOREF#410  -  []  114.11 25.58 0 top
NOREF#411  -  []  148.08 127.23 270 top
NOREF#412  -  []  51.57 101.66 0 top
NOREF#413  -  []  55.99 23.8 270 top
NOREF#414  -  []  131.8 85.29 0 top
NOREF#415  -  []  147.65 109.65 270 top
NOREF#416  -  []  153.47 150.32 90 top
NOREF#417  -  []  133.35 131.32 270 top
NOREF#418  -  []  56.82 73.14 90 top
NOREF#419  -  []  124.54 70.43 0 top
NOREF#420  -  []  149.05 151.46 0 top
NOREF#421  -  []  50.52 49.35 0 top
NOREF#422  -  []  94.69 109.91 270 top
NOREF#423  -  []  56.46 98.12 0 top
NOREF#424  -  []  49.35 104.09 0 top
NOREF#425  -  []  158.57 25.98 270 top
NOREF#426  -  []  55.37 58.25 270 top
NOREF#427  -  []  81.99 27.47 0 top
NOREF#428  -  []  25.07 28.54 90 top
NOREF#429  -  []  121.11 171.75 270 top
NOREF#430  -  []  75.01 98.6 0 top
NOREF#431  -  []  56.16 78.16 0 top
NOREF#432  -  []  127.67 73.91 0 top
NOREF#433  -  []  14.76 20.47 90 top
NOREF#434  -  []  100.48 93.59 90 top
NOREF#435  -  []  89.65 30.48 0 top
NOREF#436  -  []  43.94 34.43 270 top
NOREF#437  -  []  51.46 150.75 0 top
NOREF#438  -  []  19.63 108.79 0 top
NOREF#439  -  []  121.79 133.5 90 top
NOREF#440  -  []  66.51 91.07 90 top
NOREF#441  -  []  127.99 65.86 0 top
NOREF#442  -  []  44.25 125.78 270 top
NOREF#443  -  []  95.82 25.58 0 top
NOREF#444  -  []  150.88 178.05 0 top
NOREF#445  -  []  64.87 2.26 0 top
NOREF#446  -  []  156.41 191.47 90 top
NOREF#447  -  []  61.8 82.63 0 top
NOREF#448  -  []  95 17.44 90 top
NOREF#449  -  []  73.56 76.07 0 top
NOREF#450  -  []  34.75 32.12 0 top
NOREF#451  -  []  139.57 179.32 0 top
NOREF#452  -  []  166.07 76.76 270 top
NOREF#453  -  []  74.52 108.15 90 top
NOREF#454  -  []  139.12 103.81 270 top
NOREF#455  -  []  76.89 107.11 270 top
NOREF#456  -  []  54.48 51.82 90 top
NOREF#457  -  []  70.33 143.46 0 top
NOREF#458  -  []  47.32 28.97 0 top
NOREF#459  -  []  45.42 63.2 0 top
NOREF#460  -  []  -10.06 75.64 90 top
NOREF#461  -  []  91.43 31.37 0 top
NOREF#462  -  []  85.88 177.29 0 top
NOREF#463  -  []  68.59 89.52 0 top
NOREF#464  -  []  89 106.63 0 top
NOREF#465  -  []  133.73 54.98 90 top
NOREF#466  -  []  69.65 84.05 0 top
NOREF#467  -  []  100.28 26.71 0 top
NOREF#468  -  []  135.84 56.34 90 top
NOREF#469  -  []  140.49 133.35 0 top
NOREF#470  -  []  124 26.34 270 top
NOREF#471  -  []  72.29 83.92 270 top
NOREF#472  -  []  139.42 101.04 0 top
NOREF#473  -  []  65.35 26.34 0 top
NOREF#474  -  []  135.36 89.97 0 top
NOREF#475  -  []  146.86 102.67 270 top
NOREF#476  -  []  49.35 107.24 0 top
NOREF#477  -  []  56.63 23.8 270 top
NOREF#478  -  []  51.94 48.92 90 top
NOREF#479  -  []  5.74 118.62 0 top
NOREF#480  -  []  54.56 40.94 270 top
NOREF#481  -  []  132.36 164.21 0 top
NOREF#482  -  []  52.27 75.62 270 top
NOREF#483  -  []  115.04 85.67 90 top
NOREF#484  -  []  139.98 89.92 0 top
NOREF#485  -  []  141.58 149.38 90 top
NOREF#486  -  []  120.88 44.15 0 top
NOREF#487  -  []  87.35 92.51 0 top
NOREF#488  -  []  142.95 120.47 0 top
NOREF#489  -  []  126.44 155.02 0 top
NOREF#490  -  []  135.22 39.14 270 top
NOREF#491  -  []  17.3 114.58 0 top
NOREF#492  -  []  83.65 52.39 90 top
NOREF#493  -  []  126.9 99.57 0 top
NOREF#494  -  []  139.06 184.11 270 top
NOREF#495  -  []  135.31 184.45 270 top
NOREF#496  -  []  66.19 51.33 0 top
NOREF#497  -  []  15.32 20.78 90 top
NOREF#498  -  []  142.42 127.2 90 top
NOREF#499  -  []  95.15 58.04 0 top
NOREF#500  -  []  17.68 79.65 90 top
NOREF#501  -  []  58.43 113.3 270 top
NOREF#502  -  []  118.54 26.42 0 top
NOREF#503  -  []  40.39 93.22 270 top
NOREF#504  -  []  133.16 25.96 0 top
NOREF#505  -  []  144.98 192.33 0 top
NOREF#506  -  []  117.93 173.56 0 top
NOREF#507  -  []  101.42 64.06 270 top
NOREF#508  -  []  38.96 103.58 0 top
NOREF#509  -  []  127.47 132.23 0 top
NOREF#510  -  []  120.02 170.43 90 top
NOREF#511  -  []  109.68 30.47 90 top
NOREF#512  -  []  117.6 43.28 270 top
NOREF#513  -  []  75.46 100.46 0 top
NOREF#514  -  []  92 27.44 270 top
NOREF#515  -  []  78.99 34.43 270 top
NOREF#516  -  []  46.05 145.72 0 top
NOREF#517  -  []  65.05 51.33 0 top
NOREF#518  -  []  70.99 31.51 0 top
NOREF#519  -  []  134.06 149.3 90 top
NOREF#520  -  []  123.77 46.48 0 top
NOREF#521  -  []  98.64 38.75 270 top
NOREF#522  -  []  140.34 78.27 90 top
NOREF#523  -  []  17.98 30.98 90 top
NOREF#524  -  []  146.41 88.95 0 top
NOREF#525  -  []  119.96 170.13 0 top
NOREF#526  -  []  66.23 91.68 0 top
NOREF#527  -  []  140.97 26.67 0 top
NOREF#528  -  []  124.45 44.7 0 top
NOREF#529  -  []  62.11 109.43 90 top
NOREF#530  -  []  142.19 134.92 0 top
NOREF#531  -  []  85.29 108.79 0 top
NOREF#532  -  []  120.85 18.72 0 top
NOREF#533  -  []  75.08 37.52 0 top
NOREF#534  -  []  145.69 99.19 90 top
NOREF#535  -  []  95.45 102.95 90 top
NOREF#536  -  []  127.76 36.35 90 top
NOREF#537  -  []  127.89 143.5 270 top
NOREF#538  -  []  112.27 35.89 90 top
NOREF#539  -  []  150.57 178.64 0 top
NOREF#540  -  []  74.41 36.27 0 top
NOREF#541  -  []  51.57 100.9 0 top
NOREF#542  -  []  122.3 170.43 90 top
NOREF#543  -  []  89.61 28.05 0 top
NOREF#544  -  []  54.56 113.3 270 top
NOREF#545  -  []  62.26 172.97 0 top
NOREF#546  -  []  126.57 50.81 0 top
NOREF#547  -  []  82.14 104.85 90 top
NOREF#548  -  []  65.48 177.34 0 top
NOREF#549  -  []  76.89 103.17 270 top
NOREF#550  -  []  95.82 25.58 90 top
NOREF#551  -  []  145.62 141.58 0 top
NOREF#552  -  []  61.47 112.99 270 top
NOREF#553  -  []  139.24 120.22 90 top
NOREF#554  -  []  70.49 108.33 90 top
NOREF#555  -  []  83.9 33.92 0 top
NOREF#556  -  []  67.72 79.53 0 top
NOREF#557  -  []  53.07 30.48 0 top
NOREF#558  -  []  34.28 36.63 0 top
NOREF#559  -  []  120.85 17.09 90 top
NOREF#560  -  []  42.28 34.47 0 top
NOREF#561  -  []  101.8 31.7 90 top
NOREF#562  -  []  133.49 53.04 90 top
NOREF#563  -  []  126.57 51.57 0 top
NOREF#564  -  []  73.18 55.75 270 top
NOREF#565  -  []  54.81 31.51 0 top
NOREF#566  -  []  62.36 83.95 270 top
NOREF#567  -  []  62.1 60.96 270 top
NOREF#568  -  []  56.44 83.95 270 top
NOREF#569  -  []  9.86 81.46 0 top
NOREF#570  -  []  156.67 100.53 90 top
NOREF#571  -  []  112.13 23.8 270 top
NOREF#572  -  []  46.81 34.24 90 top
NOREF#573  -  []  48.92 76.48 0 top
NOREF#574  -  []  119.53 135.64 0 top
NOREF#575  -  []  130.63 127.3 0 top
NOREF#576  -  []  53.07 27.56 0 top
NOREF#577  -  []  58.85 109.78 270 top
NOREF#578  -  []  88.13 33.48 0 top
NOREF#579  -  []  62.31 91.64 270 top
NOREF#580  -  []  135.63 18.41 90 top
NOREF#581  -  []  129.27 42.24 0 top
NOREF#582  -  []  88.72 37.86 0 top
NOREF#583  -  []  106.69 33.48 90 top
NOREF#584  -  []  50.52 50.5 0 top
NOREF#585  -  []  36.4 128.32 0 top
NOREF#586  -  []  63.6 64.34 90 top
NOREF#587  -  []  135.69 88.39 0 top
NOREF#588  -  []  124.41 154.74 270 top
NOREF#589  -  []  98.55 36.06 90 top
NOREF#590  -  []  53.04 26.43 270 top
NOREF#591  -  []  145.44 187.45 0 top
NOREF#592  -  []  144.37 100.51 270 top
NOREF#593  -  []  54.81 27.17 0 top
NOREF#594  -  []  145.44 188.59 0 top
NOREF#595  -  []  92.08 25.26 90 top
NOREF#596  -  []  123.95 154.31 270 top
NOREF#597  -  []  140.16 139.47 0 top
NOREF#598  -  []  144.73 134.54 0 top
NOREF#599  -  []  37.82 95.07 0 top
NOREF#600  -  []  91.72 59.59 0 top
NOREF#601  -  []  157.05 184.92 0 top
NOREF#602  -  []  51.94 12.52 270 top
NOREF#603  -  []  113.28 35.89 90 top
NOREF#604  -  []  119.08 180.42 90 top
NOREF#605  -  []  108.2 36.59 270 top
NOREF#606  -  []  122.68 26.29 0 top
NOREF#607  -  []  98.42 96.51 0 top
NOREF#608  -  []  120.51 28.19 0 top
NOREF#609  -  []  85.17 27.06 0 top
NOREF#610  -  []  145.95 99.23 90 top
NOREF#611  -  []  138.91 77.93 90 top
NOREF#612  -  []  138.33 107.7 90 top
NOREF#613  -  []  124.87 2.26 0 top
NOREF#614  -  []  38.48 23.76 270 top
NOREF#615  -  []  111.49 23.8 270 top
NOREF#616  -  []  20.09 75.95 270 top
NOREF#617  -  []  85.88 191.26 0 top
NOREF#618  -  []  27.18 37.35 270 top
NOREF#619  -  []  65.23 188.16 90 top
NOREF#620  -  []  143.75 92.91 90 top
NOREF#621  -  []  126.95 41.67 270 top
NOREF#622  -  []  98.74 101.85 0 top
NOREF#623  -  []  91.64 100.95 90 top
NOREF#624  -  []  30.59 36.07 0 top
NOREF#625  -  []  89.28 110.24 0 top
NOREF#626  -  []  47.32 33.29 0 top
NOREF#627  -  []  66.92 26.92 0 top
NOREF#628  -  []  124.41 152.86 0 top
NOREF#629  -  []  46.01 138.43 0 top
NOREF#630  -  []  55.36 23.8 270 top
NOREF#631  -  []  130.56 42.28 90 top
NOREF#632  -  []  39.45 63.93 270 top
NOREF#633  -  []  38.51 37.52 0 top
NOREF#634  -  []  125.7 72.31 0 top
NOREF#635  -  []  147.7 130.77 270 top
NOREF#636  -  []  55.7 173.56 0 top
NOREF#637  -  []  44.17 102.77 90 top
NOREF#638  -  []  145.11 184.23 90 top
NOREF#639  -  []  134.37 148.21 0 top
NOREF#640  -  []  98.78 106.22 0 top
NOREF#641  -  []  116.71 17.44 90 top
NOREF#642  -  []  25.68 66.24 0 top
NOREF#643  -  []  141.55 122.15 0 top
NOREF#644  -  []  62.1 67.84 90 top
NOREF#645  -  []  126.11 33.9 90 top
NOREF#646  -  []  149.66 71.63 0 top
NOREF#647  -  []  108.71 12.52 0 top
NOREF#648  -  []  55.37 109.56 90 top
NOREF#649  -  []  71.49 33.65 90 top
NOREF#650  -  []  83.95 25.78 90 top
NOREF#651  -  []  108.28 155.27 0 top
NOREF#652  -  []  57.91 75.69 270 top
NOREF#653  -  []  56.72 77.85 270 top
NOREF#654  -  []  83.64 28.52 0 top
NOREF#655  -  []  138.89 173.69 0 top
NOREF#656  -  []  139.4 126.19 0 top
NOREF#657  -  []  101.8 33.58 0 top
NOREF#658  -  []  130.68 44.07 90 top
NOREF#659  -  []  147.14 134.54 0 top
NOREF#660  -  []  131.43 25.96 90 top
NOREF#661  -  []  66.84 100.29 270 top
NOREF#662  -  []  85.29 106.63 0 top
NOREF#663  -  []  17.98 32.63 90 top
NOREF#664  -  []  130.63 55.42 0 top
NOREF#665  -  []  34.79 26.29 0 top
NOREF#666  -  []  28.65 31.99 0 top
NOREF#667  -  []  90.53 98.86 0 top
NOREF#668  -  []  66.84 101.05 0 top
NOREF#669  -  []  74.05 36.88 270 top
NOREF#670  -  []  65.66 31.62 270 top
NOREF#671  -  []  38.56 37.2 90 top
NOREF#672  -  []  133.91 120.09 90 top
NOREF#673  -  []  65.23 33.58 270 top
NOREF#674  -  []  119.96 35.1 0 top
NOREF#675  -  []  103.3 104.7 270 top
NOREF#676  -  []  94.44 37.2 90 top
NOREF#677  -  []  123.01 154.76 270 top
NOREF#678  -  []  76.1 108.61 90 top
NOREF#679  -  []  139.61 179.07 0 top
NOREF#680  -  []  67.97 55.52 0 top
NOREF#681  -  []  21.35 39.19 90 top
NOREF#682  -  []  83.9 28.97 0 top
NOREF#683  -  []  102.27 26.04 0 top
NOREF#684  -  []  140.03 27.44 0 top
NOREF#685  -  []  121.08 32.37 90 top
NOREF#686  -  []  41.45 122.76 90 top
NOREF#687  -  []  156.7 55.37 0 top
NOREF#688  -  []  62.23 33.9 90 top
NOREF#689  -  []  42.44 110.64 0 top
NOREF#690  -  []  149.66 74.3 0 top
NOREF#691  -  []  2.03 5.84 0 top
NOREF#692  -  []  50.58 112.03 270 top
NOREF#693  -  []  79.49 36.63 0 top
NOREF#694  -  []  107.94 30.48 0 top
NOREF#695  -  []  96.33 94.74 90 top
NOREF#696  -  []  65.68 188.59 0 top
NOREF#697  -  []  29.46 191.01 0 top
NOREF#698  -  []  90.83 99.42 0 top
NOREF#699  -  []  111.12 36.31 90 top
NOREF#700  -  []  110.57 127.58 0 top
NOREF#701  -  []  55.8 56.18 270 top
NOREF#702  -  []  37.8 95.96 0 top
NOREF#703  -  []  128.57 27.06 270 top
NOREF#704  -  []  136.78 79.24 90 top
NOREF#705  -  []  102.79 28.05 90 top
NOREF#706  -  []  71.02 25.84 0 top
NOREF#707  -  []  68.71 83.82 270 top
NOREF#708  -  []  34.75 31.76 270 top
NOREF#709  -  []  95.83 101.78 90 top
NOREF#710  -  []  54.91 168.35 90 top
NOREF#711  -  []  17.27 109.22 90 top
NOREF#712  -  []  100.58 139.42 270 top
NOREF#713  -  []  54.31 150.04 0 top
NOREF#714  -  []  116.92 39.7 90 top
NOREF#715  -  []  94.21 102.39 0 top
NOREF#716  -  []  94.59 106.98 0 top
NOREF#717  -  []  62.17 91.68 0 top
NOREF#718  -  []  54.23 75.65 270 top
NOREF#719  -  []  134.52 71.5 0 top
NOREF#720  -  []  89.28 36.59 270 top
NOREF#721  -  []  55.04 35.51 90 top
NOREF#722  -  []  47.36 33.15 0 top
NOREF#723  -  []  152.91 139.95 90 top
NOREF#724  -  []  50.9 100.03 0 top
NOREF#725  -  []  134.06 149.91 0 top
NOREF#726  -  []  17.09 40.78 0 top
NOREF#727  -  []  49.35 108.38 270 top
NOREF#728  -  []  85.17 27.42 0 top
NOREF#729  -  []  58.42 37.52 270 top
NOREF#730  -  []  97.28 34.43 270 top
NOREF#731  -  []  53.05 199.26 0 top
NOREF#732  -  []  136.78 78.23 90 top
NOREF#733  -  []  107.9 28.97 270 top
NOREF#734  -  []  99.81 65.66 90 top
NOREF#735  -  []  152.01 97.93 90 top
NOREF#736  -  []  54.76 149.61 0 top
NOREF#737  -  []  125.98 154.28 270 top
NOREF#738  -  []  63.7 29.07 0 top
NOREF#739  -  []  68.53 174.42 0 top
NOREF#740  -  []  42.88 108.69 90 top
NOREF#741  -  []  30.43 31.45 0 top
NOREF#742  -  []  138.76 33.67 0 top
NOREF#743  -  []  105.41 25.78 90 top
NOREF#744  -  []  17.69 35.2 0 top
NOREF#745  -  []  89.61 32.12 0 top
NOREF#746  -  []  126.3 88.27 0 top
NOREF#747  -  []  110.03 63.11 90 top
NOREF#748  -  []  98.81 65.66 0 top
NOREF#749  -  []  33.38 193.5 0 top
NOREF#750  -  []  70.76 108.97 0 top
NOREF#751  -  []  38.96 101.3 0 top
NOREF#752  -  []  20.55 75.51 0 top
NOREF#753  -  []  126.49 36.97 270 top
NOREF#754  -  []  18.8 180.47 0 top
NOREF#755  -  []  30.86 31.9 90 top
NOREF#756  -  []  30.61 36.04 270 top
NOREF#757  -  []  57.78 72.17 90 top
NOREF#758  -  []  88.87 0.16 0 top
NOREF#759  -  []  135.97 176.45 0 top
NOREF#760  -  []  94.97 98.88 90 top
NOREF#761  -  []  133.87 54.94 90 top
NOREF#762  -  []  89.28 31.51 0 top
NOREF#763  -  []  84.91 100.63 270 top
NOREF#764  -  []  140.24 177.16 0 top
NOREF#765  -  []  49.78 104.27 0 top
NOREF#766  -  []  84.51 30.4 270 top
NOREF#767  -  []  58.08 103.59 270 top
NOREF#768  -  []  70.99 36.59 270 top
NOREF#769  -  []  39.12 104.42 90 top
NOREF#770  -  []  10.01 123.39 0 top
NOREF#771  -  []  134.62 83.59 90 top
NOREF#772  -  []  38.96 93.93 0 top
NOREF#773  -  []  36.65 178.1 0 top
NOREF#774  -  []  63.68 26.42 0 top
NOREF#775  -  []  114.68 134.96 270 top
NOREF#776  -  []  85.2 26.92 0 top
NOREF#777  -  []  150.57 191.69 270 top
NOREF#778  -  []  51.64 73.46 0 top
NOREF#779  -  []  116.13 132.66 0 top
NOREF#780  -  []  117.23 34.47 270 top
NOREF#781  -  []  68.83 57.4 270 top
NOREF#782  -  []  51.84 76.07 270 top
NOREF#783  -  []  131.27 36.61 90 top
NOREF#784  -  []  53.34 36.59 270 top
NOREF#785  -  []  50.44 100.46 270 top
NOREF#786  -  []  113.23 151.33 90 top
NOREF#787  -  []  153.09 91.62 270 top
NOREF#788  -  []  89.65 27.56 0 top
NOREF#789  -  []  123.05 41.59 90 top
NOREF#790  -  []  141 126.62 0 top
NOREF#791  -  []  53.04 30.62 270 top
NOREF#792  -  []  63.7 27.47 0 top
NOREF#793  -  []  73.38 108.15 90 top
NOREF#794  -  []  52.73 78.16 0 top
NOREF#795  -  []  34.75 28.05 0 top
NOREF#796  -  []  137.97 128.07 270 top
NOREF#797  -  []  43 68.76 0 top
NOREF#798  -  []  139.37 34.02 90 top
NOREF#799  -  []  39.45 63.07 0 top
NOREF#800  -  []  96.52 95.75 0 top
NOREF#801  -  []  53.2 36.63 270 top
NOREF#802  -  []  43.31 112.52 270 top
NOREF#803  -  []  115.77 73.58 270 top
NOREF#804  -  []  91.43 27.3 0 top
NOREF#805  -  []  115.39 121.21 0 top
NOREF#806  -  []  104.87 2.26 0 top
NOREF#807  -  []  65.61 33.29 0 top
NOREF#808  -  []  133.22 93.08 90 top
NOREF#809  -  []  30.86 33.57 90 top
NOREF#810  -  []  122.25 70.43 0 top
NOREF#811  -  []  73.18 56.9 270 top
NOREF#812  -  []  125.88 58.13 90 top
NOREF#813  -  []  47.93 30.4 270 top
NOREF#814  -  []  17.78 109.22 90 top
NOREF#815  -  []  130.25 173.81 0 top
NOREF#816  -  []  130.94 141.95 270 top
NOREF#817  -  []  151.59 151.46 0 top
NOREF#818  -  []  98.81 34.43 270 top
NOREF#819  -  []  136.73 35.89 90 top
NOREF#820  -  []  137.77 77.93 90 top
NOREF#821  -  []  82.5 56.79 0 top
NOREF#822  -  []  47.8 144.7 270 top
NOREF#823  -  []  61.14 53.09 0 top
NOREF#824  -  []  136.02 36.35 90 top
NOREF#825  -  []  146.25 95.33 0 top
NOREF#826  -  []  141.78 104.19 270 top
NOREF#827  -  []  140.59 50.29 90 top
NOREF#828  -  []  52.32 54.51 90 top
NOREF#829  -  []  14.76 22.1 0 top
NOREF#830  -  []  56.26 55.88 270 top
NOREF#831  -  []  53.04 32.4 270 top
NOREF#832  -  []  49.81 104.52 0 top
NOREF#833  -  []  127.2 75.77 0 top
NOREF#834  -  []  28.52 168.61 270 top
NOREF#835  -  []  52.74 31.65 0 top
NOREF#836  -  []  89.28 32.42 0 top
NOREF#837  -  []  76.71 37.52 270 top
NOREF#838  -  []  98.51 96.01 0 top
NOREF#839  -  []  134.06 148.67 0 top
NOREF#840  -  []  65.13 65.2 0 top
NOREF#841  -  []  64.58 102.12 270 top
NOREF#842  -  []  51.69 33.52 90 top
NOREF#843  -  []  61.8 172.54 0 top
NOREF#844  -  []  133.38 135.13 0 top
NOREF#845  -  []  97.61 25.62 90 top
NOREF#846  -  []  144.98 102.95 0 top
NOREF#847  -  []  73.33 37.39 270 top
NOREF#848  -  []  128.61 42.52 270 top
NOREF#849  -  []  72.29 83.92 270 top
NOREF#850  -  []  137.39 88.82 270 top
NOREF#851  -  []  104.39 26.29 0 top
NOREF#852  -  []  153.47 147.65 90 top
NOREF#853  -  []  75.14 37.2 90 top
NOREF#854  -  []  65.35 28.52 0 top
NOREF#855  -  []  50.06 51.71 0 top
NOREF#856  -  []  137.46 27.37 270 top
NOREF#857  -  []  47.37 186.98 90 top
NOREF#858  -  []  100.04 97.92 0 top
NOREF#859  -  []  93.21 23.8 0 top
NOREF#860  -  []  127.58 164.01 0 top
NOREF#861  -  []  144.7 103.81 270 top
NOREF#862  -  []  60.83 17.4 90 top
NOREF#863  -  []  19.8 34.29 0 top
NOREF#864  -  []  110.54 140.13 270 top
NOREF#865  -  []  65.23 188.16 0 top
NOREF#866  -  []  17.91 65.44 0 top
NOREF#867  -  []  28.75 30.56 0 top
NOREF#868  -  []  156.54 182.83 90 top
NOREF#869  -  []  47.8 146.13 90 top
NOREF#870  -  []  80.12 36.02 0 top
NOREF#871  -  []  136.22 63.45 90 top
NOREF#872  -  []  127.52 64.9 0 top
NOREF#873  -  []  97.13 95.75 90 top
NOREF#874  -  []  149.66 72.77 0 top
NOREF#875  -  []  63.96 102.08 270 top
NOREF#876  -  []  80.66 33.86 90 top
NOREF#877  -  []  107.57 36.59 270 top
NOREF#878  -  []  79.13 34.47 270 top
NOREF#879  -  []  152.2 19.56 90 top
NOREF#880  -  []  45.97 138.68 0 top
NOREF#881  -  []  128.03 143.54 270 top
NOREF#882  -  []  74.85 86.87 0 top
NOREF#883  -  []  123.25 65.53 0 top
NOREF#884  -  []  54.78 146.18 0 top
NOREF#885  -  []  97.13 96.79 90 top
NOREF#886  -  []  30.78 191.57 270 top
NOREF#887  -  []  135.25 136.27 0 top
NOREF#888  -  []  144.86 180.29 90 top
NOREF#889  -  []  70.31 38.09 90 top
NOREF#890  -  []  139.55 107.39 90 top
NOREF#891  -  []  30.3 29.26 0 top
NOREF#892  -  []  75.01 101.42 0 top
NOREF#893  -  []  76.89 102.03 270 top
NOREF#894  -  []  80.09 40.54 270 top
NOREF#895  -  []  62.42 101.51 0 top
NOREF#896  -  []  135.24 44.7 0 top
NOREF#897  -  []  62.94 177.34 270 top
NOREF#898  -  []  47.62 30.65 90 top
NOREF#899  -  []  99.61 95.26 90 top
NOREF#900  -  []  131.83 141.74 270 top
NOREF#901  -  []  123.53 64.92 90 top
NOREF#902  -  []  47.93 32.37 90 top
NOREF#903  -  []  122.25 137.11 270 top
NOREF#904  -  []  103.49 26.92 0 top
NOREF#905  -  []  30.18 36.5 270 top
NOREF#906  -  []  53.54 113.3 270 top
NOREF#907  -  []  79.62 34.47 0 top
NOREF#908  -  []  70.76 82.91 270 top
NOREF#909  -  []  111 23.76 270 top
NOREF#910  -  []  66.57 103.66 0 top
NOREF#911  -  []  26.78 38.94 0 top
NOREF#912  -  []  140.59 44.32 90 top
NOREF#913  -  []  66.37 97.61 0 top
NOREF#914  -  []  55.5 51.82 90 top
NOREF#915  -  []  122.22 133.05 90 top
NOREF#916  -  []  46.89 76.07 270 top
NOREF#917  -  []  17.22 53.8 0 top
NOREF#918  -  []  33.78 28.7 90 top
NOREF#919  -  []  128.75 65.04 0 top
NOREF#920  -  []  130.56 24.14 270 top
NOREF#921  -  []  62.05 109.74 0 top
NOREF#922  -  []  126.57 53.23 0 top
NOREF#923  -  []  63.2 66.75 0 top
NOREF#924  -  []  132.21 157.95 270 top
NOREF#925  -  []  63.96 91.11 90 top
NOREF#926  -  []  61.19 70.31 0 top
